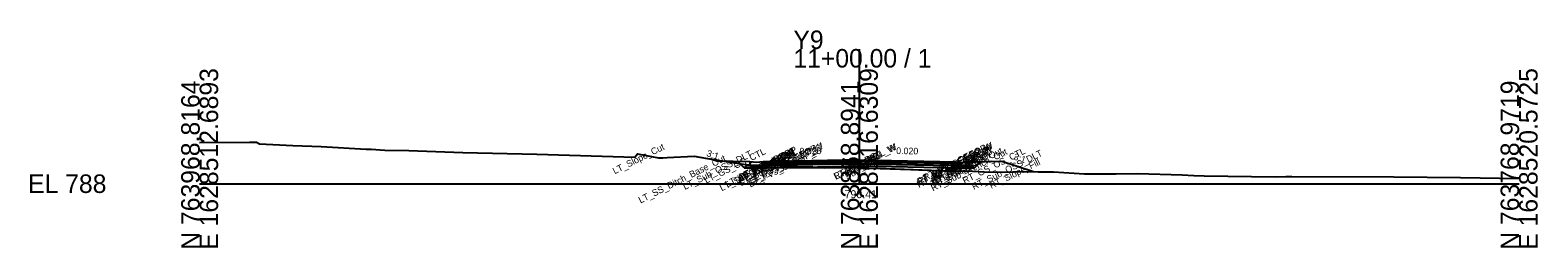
# Model space of a CAD drawing. Extents: x -26 to 203, y -10 to 6017.
# Drawn here: x -25.7 to 202.8, y 1990.3 to 2023.2 of the extents above; entities that cross this region are included whole.
import ezdxf

# ---------------------------------------------------------------- set-up
doc = ezdxf.new("R2010")
doc.units = 0
for name, color, linetype in [('Default', 7, 'Continuous'), ('Exist Cross Section Cell', 7, 'Continuous'), ('Exist XS Center Line Elevation Label', 7, 'Continuous'), ('Exist XS Ground Line', 7, 'Continuous'), ('Prop CMT Concrete Structures', 7, 'Continuous'), ('Prop CMT Pvmt Course 1', 7, 'Continuous'), ('Prop CMT Pvmt Course 1 Wedge', 7, 'Continuous'), ('Prop CMT Pvmt Course 2', 7, 'Continuous'), ('Prop CMT Pvmt Course 2 Wedge', 7, 'Continuous'), ('Prop CMT Pvmt Course 3', 7, 'Continuous'), ('Prop CMT Pvmt Course 3 Wedge', 7, 'Continuous'), ('Prop CMT Pvmt Surface', 7, 'Continuous'), ('Prop CMT Pvmt Surface Shoulder', 7, 'Continuous'), ('Prop CMT Pvmt Wedge Surface 1', 7, 'Continuous'), ('Prop CMT Pvmt Wedge Surface 2', 7, 'Continuous'), ('Prop CMT Pvmt Wedge Surface 3', 7, 'Continuous'), ('Prop CMT Shld Paved Course 1', 7, 'Continuous'), ('Prop CMT Shld Paved Course 2', 7, 'Continuous'), ('Prop CMT Shld Paved Course 3', 7, 'Continuous'), ('Prop CMT Slope Grass', 7, 'Continuous'), ('Prop CMT Subgrade Earthwork', 7, 'Continuous'), ('Prop XS SE Text', 7, 'Continuous'), ('Prop XS Side Slope Text', 7, 'Continuous'), ('Scratch_Level_0', 7, 'Continuous')]:
    doc.layers.add(name, color=color, linetype=linetype)

msp = doc.modelspace()

# ---------------------------------------------------------------- linework, layer by layer
at = {"layer": 'Exist Cross Section Cell'}
for p, q in [((100, 2000), (100, 2020.37)), ((0, 2000), (100, 2000)), ((100, 2000), (200, 2000))]:
    msp.add_line(p, q, dxfattribs=at)
at = {"layer": 'Exist XS Ground Line'}
msp.add_lwpolyline([(0, 2006.24), (7.54, 2006.3), (8.64, 2006.3), (9.05, 2006.04), (14.11, 2005.8), (18.44, 2005.63), (25.23, 2005.2), (26, 2005.2), (28.07, 2005.08), (31.71, 2005), (39.88, 2004.7), (51.1, 2004.49), (65.96, 2004), (66.38, 2004.5), (69.54, 2003.91), (70.2, 2003.92), (70.84, 2003.95), (74.98, 2004.15), (77.82, 2003.68), (82.44, 2002.97), (86.01, 2002.62), (86.4, 2002.51), (87.04, 2002.43), (90.18, 2002.43), (94.74, 2002.41), (98.46, 2002.46), (100, 2002.41), (107.82, 2002.13), (113.98, 2001.9), (116.26, 2001.94), (118.91, 2001.77), (121.72, 2001.73), (124.71, 2001.86), (127.08, 2001.81), (129.41, 2001.81), (134.12, 2001.49), (138.9, 2001.5), (142.23, 2001.55), (148.95, 2001.34), (150.7, 2001.22), (152.24, 2001.2), (163.01, 2001.06), (164.63, 2001.07), (165.57, 2001.07), (181.01, 2001.04), (191.1, 2000.95), (200, 2000.8)], dxfattribs=at)
at = {"layer": 'Prop CMT Concrete Structures'}
for points in [[(83.4, 2003.31), (83.4, 2002.73), (85.4, 2002.73)], [(85.4, 2003.31), (84.4, 2003.23), (83.4, 2003.31)], [(85.4, 2002.73), (85.4, 2003.31)], [(116.6, 2003.31), (116.6, 2002.73), (114.6, 2002.73)], [(114.6, 2003.31), (115.6, 2003.23), (116.6, 2003.31)], [(114.6, 2002.73), (114.6, 2003.31)]]:
    msp.add_lwpolyline(points, dxfattribs=at)
at = {"layer": 'Prop CMT Pvmt Course 1'}
for points in [[(100, 2003.61), (85.4, 2003.31)], [(85.4, 2003.06), (100, 2003.36)], [(85.4, 2003.31), (85.4, 2003.06)], [(86.01, 2003.2), (100, 2003.48)], [(86.01, 2003.33), (86.01, 2003.2)], [(100, 2003.61), (88.01, 2003.37)], [(100, 2003.48), (100, 2003.61)], [(100, 2003.36), (100, 2003.61)], [(100, 2003.61), (113.6, 2003.33)], [(100, 2003.48), (100, 2003.61)], [(100, 2003.61), (114.6, 2003.31)], [(100, 2003.36), (100, 2003.61)], [(113.98, 2003.2), (100, 2003.48)], [(114.6, 2003.06), (100, 2003.36)], [(113.98, 2003.33), (113.98, 2003.2)], [(114.6, 2003.31), (114.6, 2003.06)]]:
    msp.add_lwpolyline(points, dxfattribs=at)
at = {"layer": 'Prop CMT Pvmt Course 1 Wedge'}
for points in [[(86.01, 2003.08), (86.01, 2003.2)], [(88.01, 2003.24), (92.92, 2003.34), (98.46, 2003.45), (100, 2003.48)], [(100, 2003.36), (98.46, 2003.32), (92.92, 2003.21), (88.01, 2003.12)], [(100, 2003.48), (100, 2003.36)], [(100, 2003.48), (104.04, 2003.4), (113.6, 2003.21)], [(100, 2003.36), (100, 2003.48)], [(113.6, 2003.08), (104.04, 2003.27), (100, 2003.36)], [(113.98, 2003.2), (113.98, 2003.08)]]:
    msp.add_lwpolyline(points, dxfattribs=at)
at = {"layer": 'Prop CMT Pvmt Course 2'}
for points in [[(100, 2003.36), (85.4, 2003.06)], [(85.4, 2003.06), (85.4, 2002.73)], [(85.4, 2002.73), (86.01, 2002.74)], [(100, 2003.02), (100, 2003.36)], [(100, 2003.02), (100, 2003.36)], [(100, 2003.36), (114.6, 2003.06)], [(114.6, 2002.73), (113.98, 2002.74)], [(114.6, 2003.06), (114.6, 2002.73)]]:
    msp.add_lwpolyline(points, dxfattribs=at)
at = {"layer": 'Prop CMT Pvmt Course 2 Wedge'}
for points in [[(86.01, 2002.74), (86.01, 2003.08)], [(88.01, 2003.12), (92.92, 2003.21), (98.46, 2003.32), (100, 2003.36)], [(100, 2003.02), (98.46, 2002.99), (92.92, 2002.88), (88.01, 2002.78)], [(100, 2003.36), (100, 2003.02)], [(100, 2003.36), (104.04, 2003.27), (113.6, 2003.08)], [(100, 2003.02), (100, 2003.36)], [(113.6, 2002.75), (104.04, 2002.94), (100, 2003.02)], [(113.98, 2003.08), (113.98, 2002.74)]]:
    msp.add_lwpolyline(points, dxfattribs=at)
at = {"layer": 'Prop CMT Pvmt Course 3'}
msp.add_line((116.6, 2002.73), (117.1, 2002.73), dxfattribs=at)
for points in [[(86.01, 2002.74), (85.4, 2002.73)], [(85.4, 2002.73), (85.4, 2002.4)], [(91.55, 2002.52), (100, 2002.69)], [(100, 2002.69), (100, 2003.02)], [(100, 2002.69), (100, 2003.02)], [(100, 2002.69), (114.6, 2002.4)], [(113.98, 2002.74), (114.6, 2002.73)], [(114.6, 2002.4), (113.98, 2002.41)], [(114.6, 2002.73), (114.6, 2002.4)]]:
    msp.add_lwpolyline(points, dxfattribs=at)
at = {"layer": 'Prop CMT Pvmt Course 3 Wedge'}
for points in [[(86.01, 2002.74), (92.92, 2002.88), (98.46, 2002.99), (100, 2003.02)], [(86.01, 2002.54), (86.01, 2002.74)], [(100, 2002.41), (98.46, 2002.46), (92.92, 2002.5), (88.01, 2002.58)], [(100, 2003.02), (100, 2002.41)], [(100, 2003.02), (104.04, 2002.94), (113.98, 2002.74)], [(100, 2002.41), (100, 2003.02)], [(113.6, 2001.92), (104.04, 2002.26), (100, 2002.41)], [(113.98, 2002.74), (113.98, 2001.91)]]:
    msp.add_lwpolyline(points, dxfattribs=at)
at = {"layer": 'Prop CMT Pvmt Surface'}
for points in [[(100, 2003.61), (85.4, 2003.31)], [(100, 2003.61), (88.01, 2003.37)], [(100, 2003.61), (114.6, 2003.31)], [(100, 2003.61), (113.6, 2003.33)]]:
    msp.add_lwpolyline(points, dxfattribs=at)
at = {"layer": 'Prop CMT Pvmt Surface Shoulder'}
for points in [[(85.4, 2003.31), (85.4, 2003.31)], [(114.6, 2003.31), (114.6, 2003.31)]]:
    msp.add_lwpolyline(points, dxfattribs=at)
at = {"layer": 'Prop CMT Pvmt Wedge Surface 1'}
for points in [[(86.01, 2003.2), (86.01, 2003.33)], [(100, 2003.48), (88.01, 2003.24)], [(100, 2003.48), (113.6, 2003.21)], [(113.98, 2003.2), (113.98, 2003.33)]]:
    msp.add_lwpolyline(points, dxfattribs=at)
at = {"layer": 'Prop CMT Pvmt Wedge Surface 2'}
for points in [[(86.01, 2003.08), (86.01, 2003.33)], [(100, 2003.36), (88.01, 2003.12)], [(100, 2003.36), (100, 2003.61)], [(100, 2003.36), (100, 2003.61)], [(100, 2003.36), (100, 2003.61)], [(100, 2003.36), (100, 2003.61)], [(100, 2003.36), (113.6, 2003.08)], [(113.98, 2003.08), (113.98, 2003.33)]]:
    msp.add_lwpolyline(points, dxfattribs=at)
at = {"layer": 'Prop CMT Pvmt Wedge Surface 3'}
for points in [[(86.01, 2002.74), (86.01, 2003.33)], [(100, 2003.02), (86.01, 2002.74)], [(100, 2003.02), (100, 2003.61)], [(100, 2003.02), (100, 2003.61)], [(100, 2003.02), (100, 2003.61)], [(100, 2003.02), (100, 2003.61)], [(100, 2003.02), (113.98, 2002.74)], [(113.98, 2002.74), (113.98, 2003.33)]]:
    msp.add_lwpolyline(points, dxfattribs=at)
at = {"layer": 'Prop CMT Shld Paved Course 1'}
for points in [[(85.4, 2003.31), (85.4, 2003.31)], [(85.4, 2003.06), (85.4, 2003.31)], [(114.6, 2003.31), (114.6, 2003.31)], [(114.6, 2003.06), (114.6, 2003.31)]]:
    msp.add_lwpolyline(points, dxfattribs=at)
at = {"layer": 'Prop CMT Shld Paved Course 2'}
for p, q in [((83.4, 2002.73), (85.4, 2002.73)), ((116.6, 2002.73), (114.6, 2002.73))]:
    msp.add_line(p, q, dxfattribs=at)
for points in [[(85.4, 2002.73), (85.4, 2003.06)], [(114.6, 2002.73), (114.6, 2003.06)]]:
    msp.add_lwpolyline(points, dxfattribs=at)
at = {"layer": 'Prop CMT Shld Paved Course 3'}
for p, q in [((82.56, 2002.39), (85.4, 2002.4)), ((117.44, 2002.39), (114.6, 2002.4))]:
    msp.add_line(p, q, dxfattribs=at)
for points in [[(85.4, 2002.73), (83.4, 2002.73), (82.9, 2002.73), (82.56, 2002.39)], [(85.4, 2002.4), (85.4, 2002.73)], [(114.6, 2002.4), (114.6, 2002.73)], [(114.6, 2002.73), (117.1, 2002.73), (117.1, 2002.73), (117.44, 2002.39)]]:
    msp.add_lwpolyline(points, dxfattribs=at)
at = {"layer": 'Prop CMT Slope Grass'}
for points in [[(83.4, 2003.31), (78.4, 2003.41), (77.37, 2003.76)], [(116.6, 2003.31), (121.6, 2003.41), (126.37, 2001.82)]]:
    msp.add_lwpolyline(points, dxfattribs=at)
at = {"layer": 'Prop CMT Subgrade Earthwork'}
for p, q in [((82.56, 2002.39), (81.6, 2003.35)), ((85.4, 2002.4), (82.56, 2002.39)), ((86.01, 2002.41), (86.01, 2002.62)), ((113.98, 2001.9), (113.98, 2002.41)), ((114.6, 2002.4), (117.44, 2002.39)), ((117.44, 2002.39), (118.4, 2003.35))]:
    msp.add_line(p, q, dxfattribs=at)
for points in [[(86.01, 2002.41), (85.4, 2002.4)], [(113.98, 2002.41), (114.6, 2002.4)]]:
    msp.add_lwpolyline(points, dxfattribs=at)

# ---------------------------------------------------------------- texts
at = {"layer": 'Default'}
msp.add_text('-', height=0.0001, dxfattribs=at).set_placement((0, 2000))
at = {"layer": 'Exist Cross Section Cell'}
for s, p in [('Y9', (90, 2020.37)), ('11+00.00 / 1', (90, 2017.57)), ('EL 788', (-26, 1998.6))]:
    msp.add_text(s, height=2.8, dxfattribs=at).set_placement(p)
for s, p in [('E 1628512.6893', (2.8, 1990)), ('E 1628516.6309', (102.8, 1990)), ('E 1628520.5725', (202.8, 1990)), ('N 763968.8164', (0, 1990)), ('N 763868.8941', (100, 1990)), ('N 763768.9719', (200, 1990))]:
    msp.add_text(s, height=2.8, rotation=90, dxfattribs=at).set_placement(p)
at = {"layer": 'Exist XS Center Line Elevation Label'}
msp.add_text('790.41', height=1.2, dxfattribs=at).set_placement((97.76, 1997.81))
at = {"layer": 'Prop XS SE Text'}
for rotation, p in [(1.1458, (90.93, 2004.42)), (358.8542, (105.57, 2004.49))]:
    msp.add_text('0.020', height=1, rotation=rotation, dxfattribs=at).set_placement(p)
at = {"layer": 'Prop XS Side Slope Text'}
for p in [(76.74, 2004.2), (123.29, 2003.68)]:
    msp.add_text('3:1', height=1, rotation=341.5651, dxfattribs=at).set_placement(p)
at = {"layer": 'Scratch_Level_0'}
for s, p in [('LT_Slope_Cut', (62.91, 2001.41)), ('LT_SS_Ditch_Base_Out', (66.82, 1997)), ('LT_Sub_OSS_DLT', (73.56, 1999.04)), ('LT_GS_OS_CTL', (76.79, 1999.99)), ('LT_Sub_Trench_Out', (79.14, 1998.84)), ('LT_PS3_Shelf_Out', (79.97, 1999.42)), ('LT_PS3_OEOP', (81.48, 1999.94)), ('LT_PS2_OEOP', (81.82, 2000.28)), ('LT_PV2_OEOT', (82.04, 2000.27)), ('LT_PV3_OEOT', (82.04, 1999.93)), ('LT_Sub_OEOT', (82.06, 1999.61)), ('LT_PV1_OEOT', (82.15, 2000.57)), ('LT_PS1_OEOP', (82.19, 2000.59)), ('LT_PV2_OEEOP_W', (83.48, 1999.73)), ('LT_PV3_OEEOP_W', (83.48, 1999.4)), ('LT_PV1_OEEOP_W', (83.59, 1999.91)), ('LT_PV1_OEEOP', (84.45, 2000.46)), ('RT_PV1_PGL_W', (96.41, 2000.57)), ('LT_PV1_PGL_W', (96.47, 2000.6)), ('PV2_PGL', (98.08, 2001.28)), ('PV3_PGL', (98.08, 2000.94)), ('PV1_PGL', (98.18, 2001.58)), ('RT_PV2_OEEOP_W', (109.02, 1999.67)), ('RT_PV3_OEEOP_W', (109.02, 1999.34)), ('RT_PV1_OEEOP_W', (109.12, 1999.85)), ('RT_PV1_OEEOP', (109.98, 2000.41)), ('RT_Sub_Trench_Out', (111.16, 1998.81)), ('RT_PV2_OEOT', (111.19, 2000.24)), ('RT_PV3_OEOT', (111.19, 1999.91)), ('RT_Sub_OEOT', (111.21, 1999.58)), ('RT_PV1_OEOT', (111.3, 2000.54)), ('RT_PS3_Shelf_Out', (111.31, 1999.4)), ('RT_PS1_OEOP', (111.33, 2000.56)), ('RT_PS2_OEOP', (111.48, 2000.25)), ('RT_PS3_OEOP', (111.82, 1999.91)), ('RT_GS_OS_CTL', (115.94, 1999.96)), ('RT_Sub_OSS_DLT', (117.35, 1999.03)), ('Sub_PGL', (98.1, 2000.62)), ('RT_Slope_Fill', (120, 1999.19))]:
    msp.add_text(s, height=1, rotation=26.5651, dxfattribs=at).set_placement(p)

doc.saveas('drawing.dxf')
